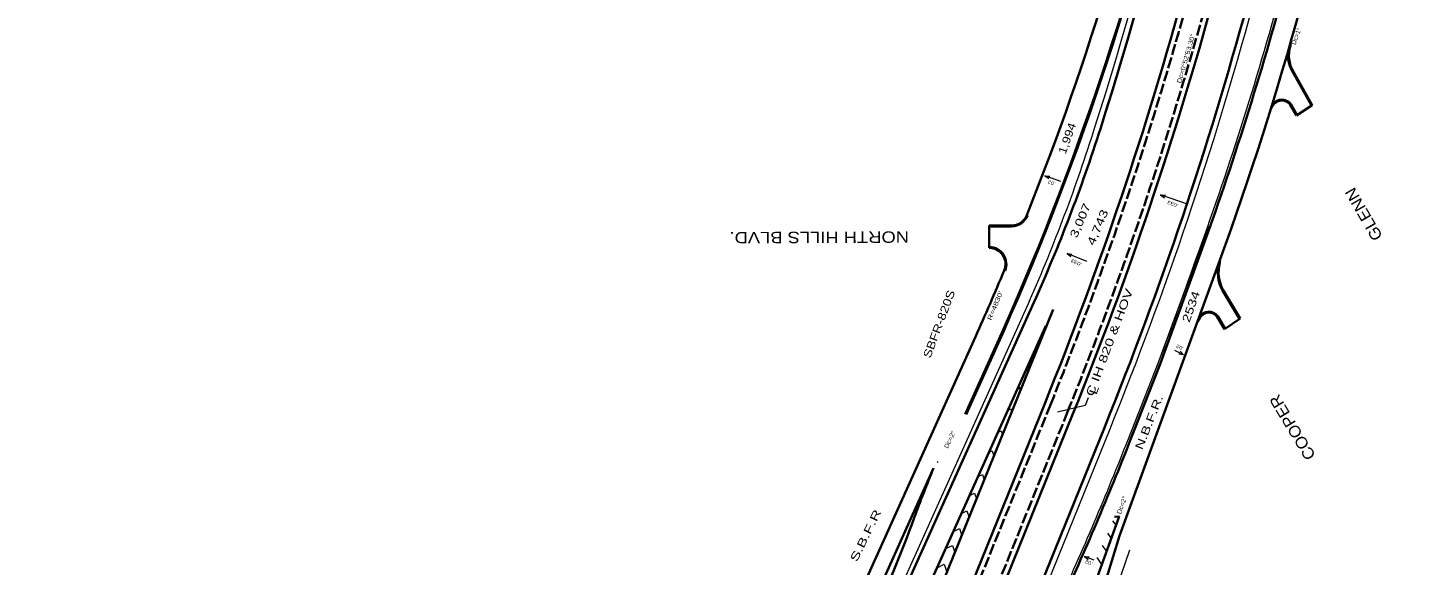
# Model space of a CAD drawing. Extents: x 2354993 to 2372084, y 6966390 to 6990057.
# Drawn here: x 2364099 to 2366527, y 6982315 to 6983254 of the extents above; entities that cross this region are included whole.
import ezdxf

# ---------------------------------------------------------------- set-up
doc = ezdxf.new("R2010")
doc.units = 0
doc.header["$LTSCALE"] = 3.2
doc.linetypes.add('LONG_DASHED', pattern=[7.5, 6, -1.5])
doc.linetypes.add('MEDIUM_DASHED', pattern=[4.5, 3, -1.5])
for name, color, linetype, lineweight in [('1', 7, 'Continuous', 13), ('11', 7, 'Continuous', 13), ('13', 7, 'Continuous', 13), ('17', 7, 'Continuous', 13), ('19', 7, 'Continuous', 13), ('2', 7, 'Continuous', 35), ('23', 7, 'Continuous', 13), ('28', 7, 'Continuous', 35), ('4', 7, 'Continuous', 13), ('5', 7, 'Continuous', 35), ('7', 7, 'Continuous', 13), ('9', 7, 'Continuous', 13)]:
    doc.layers.add(name, color=color, linetype=linetype, lineweight=lineweight)

msp = doc.modelspace()

# ---------------------------------------------------------------- linework, layer by layer
at = {"layer": '1', "lineweight": 35}
msp.add_line((2366030.231, 6982541.336), (2366077.003, 6982660.345), dxfattribs=at)
at = {"layer": '1'}
msp.add_arc((2359877.328, 6985028.057), 6596.25, 337.9611, 351.54396, dxfattribs=at)
at = {"layer": '11'}
for q in [(2366104.775, 6982690.097), (2366111.771, 6982683.473), (2366114.173, 6982688.989)]:
    msp.add_line((2366119.96, 6982682.603), q, dxfattribs=at)
at = {"layer": '13'}
msp.add_lwpolyline([(2365953.55, 6982607.162), (2365948.22, 6982593.653), (2365899.746, 6982582.544)], dxfattribs=at)
at = {"layer": '19'}
for p, q in [((2365877.738, 6982995.496), (2365884.513, 6982990.691)), ((2365877.738, 6982995.496), (2365886.033, 6982994.982)), ((2365905.646, 6982985.641), (2365877.738, 6982995.496)), ((2366080.067, 6982961.981), (2366088.367, 6982961.561)), ((2365916.553, 6982859.644), (2365924.81, 6982858.713)), ((2365946.856, 6982329.752), (2365953.6, 6982324.903)), ((2365946.856, 6982329.752), (2365955.148, 6982329.183)), ((2365963.796, 6982323.645), (2365946.856, 6982329.752))]:
    msp.add_line(p, q, dxfattribs=at)
for points in [[(2366125.148, 6982946.648), (2366080.067, 6982961.981), (2366086.9, 6982957.253)], [(2365950.852, 6982845.561), (2365916.553, 6982859.644), (2365923.08, 6982854.503)]]:
    msp.add_lwpolyline(points, dxfattribs=at)
at = {"layer": '2'}
for p, q in [((2366306.976, 6983222.524), (2366307.445, 6983227.753)), ((2366343.871, 6983118.358), (2366311.105, 6983176.578)), ((2366345.178, 6983119.094), (2366312.412, 6983177.314)), ((2366275.193, 6983116.514), (2366272.759, 6983112.093)), ((2366306.809, 6983119.535), (2366317.409, 6983100.667)), ((2366308.116, 6983120.27), (2366318.717, 6983101.402)), ((2366317.409, 6983100.667), (2366345.178, 6983119.094)), ((2365819.459, 6982908.623), (2365780.234, 6982908.603)), ((2365780.234, 6982908.603), (2365780.254, 6982869.535)), ((2365819.46, 6982907.123), (2365780.235, 6982907.103)), ((2366183.786, 6982843.837), (2366184.444, 6982849.724)), ((2366189.372, 6982795.538), (2366219.038, 6982746.109)), ((2365858.107, 6982773.741), (2365517.469, 6982017.581)), ((2366188.086, 6982794.766), (2366217.752, 6982745.337)), ((2365655.565, 6982177.229), (2365892.178, 6982761.724)), ((2366148.809, 6982746.989), (2366144.9, 6982741.33)), ((2366191.891, 6982727.318), (2366178.711, 6982749.116)), ((2366193.174, 6982728.094), (2366179.994, 6982749.892)), ((2365879.26, 6982733.049), (2365636.764, 6982194.747)), ((2366219.038, 6982746.109), (2366191.891, 6982727.318)), ((2365506.33, 6982159.631), (2365756.042, 6982713.951)), ((2365738.464, 6982578.76), (2365792.056, 6982697.727)), ((2365739.895, 6982578.274), (2365793.424, 6982697.111)), ((2365700.058, 6982159.218), (2365878.037, 6982598.874)), ((2365748.722, 6982139.518), (2365926.701, 6982579.174)), ((2365682.891, 6982484.607), (2365682.892, 6982484.609))]:
    msp.add_line(p, q, dxfattribs=at)
at = {"layer": '2', "linetype": 'LONG_DASHED'}
for p, q in [((2365709.327, 6982155.466), (2365887.306, 6982595.122)), ((2365739.453, 6982143.27), (2365917.432, 6982582.926))]:
    msp.add_line(p, q, dxfattribs=at)
at = {"layer": '2', "linetype": 'MEDIUM_DASHED', "lineweight": 13}
msp.add_line((2365688.987, 6982495.873), (2365691.036, 6982494.939), dxfattribs=at)
at = {"layer": '2'}
msp.add_lwpolyline([(2365682.892, 6982484.609), (2365562.57, 6982217.518), (2365573.511, 6982212.589)], dxfattribs=at)
for centre, radius, start, end in [((2361244.215, 6984746.454), 4988, 335.74923, 358.78496), ((2361244.215, 6984746.454), 4989.5, 335.74923, 358.78496), ((2361361.727, 6984722.767), 4830.559, 338.17176, 359.03629), ((2359877.328, 6985028.058), 6473.75, 337.9611, 351.54233), ((2359877.328, 6985028.057), 6526.25, 337.9611, 351.54396), ((2359877.328, 6985028.057), 6586.25, 337.9611, 351.54396), ((2366359.464, 6983205.904), 56.557, 162.42922, 211.23262), ((2366359.464, 6983205.904), 55.057, 162.42922, 211.23262), ((2366291.881, 6983108.766), 19.898, 35.31996, 155.09404), ((2366291.881, 6983108.766), 18.398, 35.31996, 155.09404), ((2363246.117, 6983950.399), 2864.789, 335.74921, 342.26078), ((2365819.445, 6982937.123), 28.5, 270.02906, 338.42308), ((2365819.445, 6982937.123), 30, 270.02906, 338.42308), ((2365780.269, 6982841.035), 30, 337.21464, 90.02906), ((2365780.269, 6982841.035), 28.5, 337.21464, 90.02993), ((2366247.261, 6982826.707), 67.246, 164.89773, 208.35832), ((2366247.261, 6982826.707), 65.746, 164.89773, 208.35832), ((2361116.677, 6984801.972), 5087.587, 335.7691, 337.19444), ((2366164.42, 6982738.739), 19.156, 35.60713, 152.14429), ((2366164.42, 6982738.739), 17.656, 35.60713, 152.14429), ((2368349.917, 6981400.909), 2878.789, 157.88653, 159.73969), ((2362974.286, 6983383.498), 2850.789, 335.74918, 339.77145)]:
    msp.add_arc(centre, radius, start, end, dxfattribs=at)
at = {"layer": '2', "linetype": 'LONG_DASHED'}
for centre, radius, end in [((2359877.328, 6985028.058), 6483.75, 346.60187), ((2359877.328, 6985028.057), 6516.25, 346.60718)]:
    msp.add_arc(centre, radius, 337.9611, end, dxfattribs=at)
at = {"layer": '2'}
msp.add_ellipse((2359801.786, 6985036.219), major_axis=(6478.123, 0), ratio=0.996776, start_param=5.97499933, end_param=6.13557103, dxfattribs=at)
at = {"layer": '23'}
msp.add_arc((2359111.542, 6985307.18), 7447.48, 339.24494, 340.82945, dxfattribs=at)
at = {"layer": '4'}
for p, q in [((2366073.227, 6982661.608), (2366163.84, 6982907.068)), ((2365850.813, 6982777.027), (2365510.175, 6982020.867))]:
    msp.add_line(p, q, dxfattribs=at)
at = {"layer": '4', "lineweight": 25}
for points in [[(2365846.661, 6982659.924), (2365849.126, 6982661.129), (2365850.154, 6982658.083)], [(2365830.083, 6982623.123), (2365833.69, 6982624.887), (2365835.097, 6982620.721)]]:
    msp.add_lwpolyline(points, dxfattribs=at)
at = {"layer": '4'}
for points in [[(2365813.367, 6982586.017), (2365818.081, 6982588.322), (2365819.854, 6982583.069)], [(2365795.928, 6982547.304), (2365800.887, 6982549.729), (2365803.375, 6982542.36)], [(2365779.892, 6982511.707), (2365785.684, 6982514.539), (2365788.607, 6982505.88)], [(2365760.91, 6982469.57), (2365768.52, 6982473.291), (2365771.655, 6982464.004)], [(2365746.098, 6982436.69), (2365754.652, 6982440.872), (2365758.126, 6982430.583)], [(2365731.898, 6982405.168), (2365741.237, 6982409.734), (2365745.079, 6982398.354)], [(2365717.673, 6982373.591), (2365728.082, 6982378.68), (2365732.189, 6982366.514)], [(2365704.204, 6982343.692), (2365715.987, 6982349.453), (2365720.214, 6982336.932)], [(2365689.17, 6982310.318), (2365701.705, 6982316.447), (2365706.351, 6982302.686)]]:
    msp.add_lwpolyline(points, dxfattribs=at)
for centre, radius, start, end in [((2359877.328, 6985028.058), 6391.75, 342.25932, 351.54233), ((2363191.065, 6983952.323), 2907.848, 336.16019, 342.55197)]:
    msp.add_arc(centre, radius, start, end, dxfattribs=at)
at = {"layer": '5', "lineweight": 13}
for p, q in [((2366163.734, 6982906.741), (2366163.736, 6982906.748)), ((2366023.798, 6982535.903), (2366075.709, 6982667.989)), ((2365813.607, 6982113.252), (2365991.586, 6982552.908)), ((2365996.066, 6982392.476), (2366000.581, 6982386.18)), ((2365987.02, 6982370.772), (2365992.292, 6982363.419)), ((2366025.609, 6982341.071), (2365866.293, 6981881.435)), ((2365977.842, 6982349.25), (2365984.004, 6982340.659)), ((2365968.536, 6982327.909), (2365975.715, 6982317.898))]:
    msp.add_line(p, q, dxfattribs=at)
at = {"layer": '5'}
for p, q in [((2366008.225, 6982366.256), (2366183.609, 6982847.881)), ((2366077.494, 6982661.687), (2366149.782, 6982860.199)), ((2366027.521, 6982534.44), (2366079.432, 6982666.526)), ((2365804.338, 6982117.004), (2365982.317, 6982556.66)), ((2365895.848, 6982092.73), (2366007.685, 6982399.844)), ((2366008.194, 6982399.872), (2365999.64, 6982399.403)), ((2366008.225, 6982366.256), (2365938.683, 6982140.218))]:
    msp.add_line(p, q, dxfattribs=at)
for centre, radius, start, end in [((2360811.157, 6984804.27), 5717.578, 339.9908, 358.60851), ((2360811.157, 6984804.27), 5681.578, 339.99081, 344.99116), ((2360717.318, 6984621.39), 5705.578, 335.3684, 338.5448)]:
    msp.add_arc(centre, radius, start, end, dxfattribs=at)
at = {"layer": '5', "lineweight": 13}
for centre, radius, start, end in [((2360811.157, 6984804.27), 5677.578, 339.99081, 344.99116), ((2360717.318, 6984621.39), 5701.578, 335.3684, 338.5448)]:
    msp.add_arc(centre, radius, start, end, dxfattribs=at)
at = {"layer": '9'}
msp.add_arc((2360722.521, 6984327.136), 5729.573, 359.50797, 359.50797, dxfattribs=at)

# ---------------------------------------------------------------- texts
at = {"layer": '13'}
for s, height, rotation, width, p in [('1,994', 14, 70.625, 1.2, (2365913.767, 6983032.14)), ('GLENN', 20, 119.996, 1.1, (2366469.209, 6982889.386)), ('3,007', 14, 66.892, 1.35, (2365933.429, 6982885.399)), ('4,743', 14, 67.145, 1.4, (2365963.549, 6982872.384)), ('NORTH HILLS BLVD.', 20, 180.22, 1.2, (2365639.926, 6982898.482)), ('C IH 820 & HOV ', 14, 69.296, 1.45, (2365961.818, 6982608.637)), ('SBFR-820S', 14, 69.451, 1.25, (2365677.243, 6982675.548)), ('2534', 14, 70.763, 1.35, (2366130.359, 6982737.81)), ('N.B.F.R.', 14, 68.262, 1.4, (2366047.734, 6982515.488)), ('COOPER', 20, 121.158, 1.1, (2366352.081, 6982506.215)), ('S.B.F.R', 14, 63.994, 1.5, (2365548.85, 6982319.471))]:
    msp.add_text(s, height=height, rotation=rotation, dxfattribs=dict(at, width=width)).set_placement(p)
at = {"layer": '17'}
for s, rotation, width, p in [("R=4830'", 67.249, 1.35, (2365783.775, 6982742.08)), ('Dc=2°', 64.778, 1.1, (2365708.14, 6982518.079))]:
    msp.add_text(s, height=8, rotation=rotation, dxfattribs=dict(at, width=width)).set_placement(p)
at = {"layer": '19'}
msp.add_text('Dc=1°', height=8, rotation=69.68, dxfattribs=at).set_placement((2366315.848, 6983223.82))
for s, height, rotation, width, p in [('.02', 6, 160.591, 1.25, (2365897.029, 6982983.671)), ('.033', 6, 158.267, 1.3, (2366111.984, 6982944.998)), ('.033', 6, 158.267, 1.3, (2365943.607, 6982842.629)), ('.02', 6, 154.917, 1.3, (2366121.767, 6982695.024)), ('Dc=2°', 8, 69.681, 1.1, (2366010.431, 6982403.229)), ('.02', 6, 160.217, 1.25, (2365962.252, 6982319.579))]:
    msp.add_text(s, height=height, rotation=rotation, dxfattribs=dict(at, width=width)).set_placement(p)
at = {"layer": '28', "width": 1.4}
msp.add_text('L ', height=14, rotation=69.296, dxfattribs=at).set_placement((2365967.564, 6982611.832))
at = {"layer": '7', "width": 1.2}
msp.add_text('Dc=0°52\'53.30"', height=8, rotation=73.593, dxfattribs=at).set_placement((2366115.556, 6983156.593))

doc.saveas('drawing.dxf')
